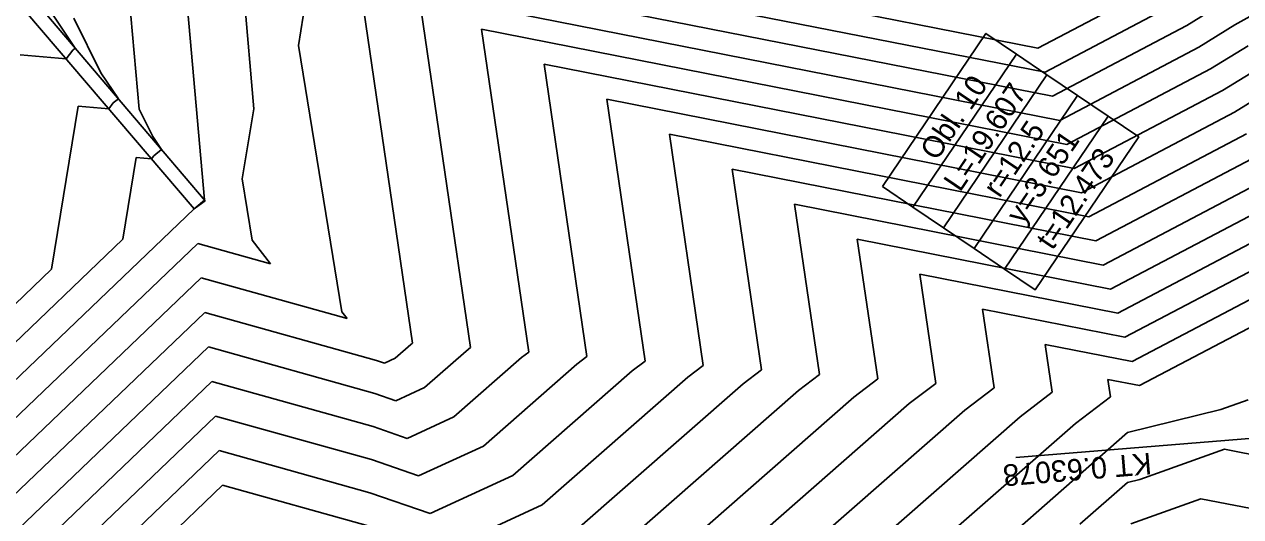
# Model space of a CAD drawing. Extents: x -549394 to -546608, y -1037055 to -1033629.
# Drawn here: x -547411.6 to -547213.9, y -1036111.6 to -1036031.6 of the extents above; entities that cross this region are included whole.
import ezdxf

# ---------------------------------------------------------------- set-up
doc = ezdxf.new("R2010")
doc.units = 0
for name, color, linetype in [('hlavni_vrst', 7, 'Continuous'), ('hrana_L', 7, 'Continuous'), ('norm_vrst', 7, 'Continuous'), ('x_popis_oblouky_C31', 7, 'Continuous')]:
    doc.layers.add(name, color=color, linetype=linetype)

msp = doc.modelspace()

# ---------------------------------------------------------------- linework, layer by layer
at = {"layer": 'hlavni_vrst'}
for p, q in [((-547385.56, -1036022.8), (-547382.3, -1036060.1)), ((-547337.27, -1036032.37), (-547329.59, -1036084.85)), ((-547242.13, -1036051.11), (-547337.27, -1036032.37)), ((-547212.7, -1036035.07), (-547218.78, -1036038.81)), ((-547218.78, -1036038.81), (-547242.13, -1036051.11)), ((-547209.1, -1036056.41), (-547236.25, -1036070.69)), ((-547382.26, -1036060.17), (-547383.95, -1036061.55)), ((-547382.3, -1036060.1), (-547382.27, -1036060.15)), ((-547382.27, -1036060.15), (-547382.26, -1036060.17)), ((-547286.38, -1036060.82), (-547282.33, -1036088.47)), ((-547236.25, -1036070.69), (-547286.38, -1036060.82)), ((-547383.95, -1036061.55), (-547529.34, -1036200.56)), ((-547383.95, -1036061.55), (-547383.95, -1036061.55)), ((-547383.95, -1036061.55), (-547383.95, -1036061.55)), ((-547383.95, -1036061.55), (-547383.95, -1036061.55)), ((-547383.95, -1036061.55), (-547383.95, -1036061.55)), ((-547383.95, -1036061.55), (-547383.95, -1036061.55)), ((-547383.95, -1036061.55), (-547383.95, -1036061.55)), ((-547383.95, -1036061.55), (-547383.95, -1036061.55)), ((-547206.64, -1036077.79), (-547230.36, -1036090.28)), ((-547330.76, -1036085.74), (-547341.74, -1036095.35)), ((-547329.59, -1036084.85), (-547330.76, -1036085.74)), ((-547282.33, -1036088.47), (-547285.75, -1036091.08)), ((-547381.07, -1036089.63), (-547506.12, -1036209.19)), ((-547354.88, -1036096.94), (-547381.07, -1036089.63)), ((-547235.49, -1036089.27), (-547235.08, -1036092.1)), ((-547230.36, -1036090.28), (-547235.49, -1036089.27)), ((-547285.75, -1036091.08), (-547317.86, -1036119.19)), ((-547235.08, -1036092.1), (-547240.75, -1036096.43)), ((-547341.74, -1036095.35), (-547349.34, -1036098.86)), ((-547240.75, -1036096.43), (-547293.98, -1036143.02)), ((-547349.34, -1036098.86), (-547354.88, -1036096.94))]:
    msp.add_line(p, q, dxfattribs=at)
at = {"layer": 'hrana_L'}
for p, q in [((-547382.19, -1036060.25), (-547409.46, -1036028.18)), ((-547411.32, -1036029.57), (-547383.95, -1036061.55)), ((-547383.95, -1036061.55), (-547382.19, -1036060.25))]:
    msp.add_line(p, q, dxfattribs=at)
at = {"layer": 'norm_vrst'}
for p, q in [((-547158.79, -1036000.4), (-547214.84, -1036031.67)), ((-547246.84, -1036035.44), (-547355.52, -1036014.04)), ((-547245.66, -1036039.35), (-547358.4, -1036017.15)), ((-547357.62, -1036020.99), (-547348.49, -1036083.4)), ((-547244.48, -1036043.27), (-547357.62, -1036020.99)), ((-547376.33, -1036021.55), (-547374.26, -1036045.33)), ((-547394.78, -1036024.05), (-547392.92, -1036045.34)), ((-547226.52, -1036024.74), (-547246.84, -1036035.44)), ((-547347.44, -1036026.68), (-547339.04, -1036084.12)), ((-547243.31, -1036047.19), (-547347.44, -1036026.68)), ((-547407.54, -1036029.1), (-547403.29, -1036035.43)), ((-547224.58, -1036028.26), (-547245.66, -1036039.35)), ((-547216.97, -1036028.27), (-547222.65, -1036031.78)), ((-547403.54, -1036030.58), (-547399.12, -1036039.45)), ((-547366.24, -1036030.25), (-547367.03, -1036035)), ((-547222.65, -1036031.78), (-547244.48, -1036043.27)), ((-547214.84, -1036031.67), (-547220.71, -1036035.3)), ((-547367.03, -1036035), (-547359.98, -1036078.3)), ((-547220.71, -1036035.3), (-547243.31, -1036047.19)), ((-547404.79, -1036037.2), (-547412.23, -1036036.52)), ((-547403.67, -1036035.75), (-547404.79, -1036037.2)), ((-547403.29, -1036035.43), (-547403.67, -1036035.75)), ((-547327.09, -1036038.06), (-547320.14, -1036085.57)), ((-547240.95, -1036055.02), (-547327.09, -1036038.06)), ((-547210.57, -1036038.46), (-547216.84, -1036042.33)), ((-547399.12, -1036039.45), (-547396.28, -1036043.68)), ((-547216.84, -1036042.33), (-547240.95, -1036055.02)), ((-547208.44, -1036041.86), (-547214.91, -1036045.85)), ((-547402.8, -1036044.86), (-547407.14, -1036071.39)), ((-547397.84, -1036045.32), (-547402.8, -1036044.86)), ((-547397.1, -1036044.35), (-547397.84, -1036045.32)), ((-547396.28, -1036043.68), (-547397.1, -1036044.35)), ((-547316.91, -1036043.75), (-547310.69, -1036086.3)), ((-547239.78, -1036058.94), (-547316.91, -1036043.75)), ((-547392.92, -1036045.34), (-547390.7, -1036049.8)), ((-547374.26, -1036045.33), (-547376.15, -1036056.66)), ((-547214.91, -1036045.85), (-547239.78, -1036058.94)), ((-547390.7, -1036049.8), (-547389.27, -1036051.92)), ((-547306.73, -1036049.44), (-547301.23, -1036087.02)), ((-547238.6, -1036062.86), (-547306.73, -1036049.44)), ((-547212.97, -1036049.37), (-547238.6, -1036062.86)), ((-547390.52, -1036052.95), (-547390.9, -1036053.43)), ((-547389.27, -1036051.92), (-547390.52, -1036052.95)), ((-547211.04, -1036052.89), (-547237.42, -1036066.77)), ((-547393.38, -1036053.21), (-547395.55, -1036066.47)), ((-547390.9, -1036053.43), (-547393.38, -1036053.21)), ((-547296.56, -1036055.13), (-547291.78, -1036087.75)), ((-547237.42, -1036066.77), (-547296.56, -1036055.13)), ((-547376.15, -1036056.66), (-547374.52, -1036066.65)), ((-547207.17, -1036059.92), (-547235.07, -1036074.61)), ((-547205.23, -1036063.44), (-547233.89, -1036078.53)), ((-547395.55, -1036066.47), (-547533.98, -1036198.84)), ((-547374.52, -1036066.65), (-547371.54, -1036070.47)), ((-547276.2, -1036066.51), (-547272.88, -1036089.2)), ((-547235.07, -1036074.61), (-547276.2, -1036066.51)), ((-547203.3, -1036066.96), (-547232.71, -1036082.44)), ((-547383.37, -1036067.17), (-547524.69, -1036202.29)), ((-547371.54, -1036070.47), (-547383.37, -1036067.17)), ((-547201.37, -1036070.48), (-547231.54, -1036086.36)), ((-547407.14, -1036071.39), (-547538.63, -1036197.11)), ((-547382.8, -1036072.78), (-547520.05, -1036204.01)), ((-547359.12, -1036079.39), (-547382.8, -1036072.78)), ((-547266.02, -1036072.2), (-547263.43, -1036089.92)), ((-547233.89, -1036078.53), (-547266.02, -1036072.2)), ((-547382.22, -1036078.4), (-547515.4, -1036205.74)), ((-547354.33, -1036086.19), (-547382.22, -1036078.4)), ((-547359.98, -1036078.3), (-547359.12, -1036079.39)), ((-547255.85, -1036077.89), (-547253.98, -1036090.65)), ((-547232.71, -1036082.44), (-547255.85, -1036077.89)), ((-547381.64, -1036084.01), (-547510.76, -1036207.47)), ((-547354.6, -1036091.56), (-547381.64, -1036084.01)), ((-547348.76, -1036083.6), (-547351.29, -1036085.82)), ((-547348.49, -1036083.4), (-547348.76, -1036083.6)), ((-547339.76, -1036084.67), (-547346.52, -1036090.59)), ((-547339.04, -1036084.12), (-547339.76, -1036084.67)), ((-547245.67, -1036083.58), (-547244.53, -1036091.37)), ((-547231.54, -1036086.36), (-547245.67, -1036083.58)), ((-547353.05, -1036086.63), (-547354.33, -1036086.19)), ((-547351.29, -1036085.82), (-547353.05, -1036086.63)), ((-547320.14, -1036085.57), (-547321.76, -1036086.81)), ((-547310.69, -1036086.3), (-547312.76, -1036087.88)), ((-547321.76, -1036086.81), (-547336.97, -1036100.12)), ((-547312.76, -1036087.88), (-547332.19, -1036104.89)), ((-547301.23, -1036087.02), (-547303.76, -1036088.94)), ((-547291.78, -1036087.75), (-547294.76, -1036090.01)), ((-547346.52, -1036090.59), (-547351.19, -1036092.74)), ((-547303.76, -1036088.94), (-547327.42, -1036109.66)), ((-547294.76, -1036090.01), (-547322.64, -1036114.42)), ((-547272.88, -1036089.2), (-547276.75, -1036092.15)), ((-547263.43, -1036089.92), (-547267.75, -1036093.22)), ((-547253.98, -1036090.65), (-547258.75, -1036094.29)), ((-547351.19, -1036092.74), (-547354.6, -1036091.56)), ((-547276.75, -1036092.15), (-547313.09, -1036123.96)), ((-547244.53, -1036091.37), (-547249.75, -1036095.36)), ((-547212.67, -1036092.59), (-547217.14, -1036094.19)), ((-547267.75, -1036093.22), (-547308.31, -1036128.72)), ((-547258.75, -1036094.29), (-547303.54, -1036133.49)), ((-547217.14, -1036094.19), (-547232.29, -1036097.92)), ((-547380.49, -1036095.24), (-547501.47, -1036210.92)), ((-547355.15, -1036102.32), (-547380.49, -1036095.24)), ((-547249.75, -1036095.36), (-547298.76, -1036138.26)), ((-547232.29, -1036097.92), (-547263.21, -1036125.03)), ((-547336.97, -1036100.12), (-547347.49, -1036104.97)), ((-547379.92, -1036100.86), (-547496.83, -1036212.64)), ((-547355.43, -1036107.7), (-547379.92, -1036100.86)), ((-547347.49, -1036104.97), (-547355.15, -1036102.32)), ((-547216.52, -1036100.64), (-547230.31, -1036105.55)), ((-547209.69, -1036101.97), (-547216.52, -1036100.64)), ((-547379.34, -1036106.47), (-547492.18, -1036214.37)), ((-547355.7, -1036113.07), (-547379.34, -1036106.47)), ((-547332.19, -1036104.89), (-547345.63, -1036111.08)), ((-547232.29, -1036106.04), (-547240.02, -1036112.82)), ((-547230.31, -1036105.55), (-547232.29, -1036106.04)), ((-547345.63, -1036111.08), (-547355.43, -1036107.7)), ((-547327.42, -1036109.66), (-547343.78, -1036117.2)), ((-547220.38, -1036108.68), (-547231.74, -1036112.73)), ((-547208.93, -1036110.91), (-547220.38, -1036108.68))]:
    msp.add_line(p, q, dxfattribs=at)
at = {"layer": 'x_popis_oblouky_C31'}
for points in [[(-547272.13, -1036057.91), (-547255.31, -1036033.06), (-547250.34, -1036036.43), (-547267.16, -1036061.27)], [(-547267.16, -1036061.27), (-547250.34, -1036036.43), (-547245.38, -1036039.79), (-547262.19, -1036064.63)], [(-547262.19, -1036064.63), (-547245.38, -1036039.79), (-547240.41, -1036043.15), (-547257.22, -1036068)], [(-547257.22, -1036068), (-547240.41, -1036043.15), (-547235.44, -1036046.52), (-547252.26, -1036071.36)], [(-547252.26, -1036071.36), (-547235.44, -1036046.52), (-547230.47, -1036049.88), (-547247.29, -1036074.72)]]:
    msp.add_lwpolyline(points, close=True, dxfattribs=at)
msp.add_lwpolyline([(-547209.19, -1036098.59), (-547250.42, -1036101.99)], dxfattribs=at)

# ---------------------------------------------------------------- texts
for s, rotation, p in [('Obl. 10', 55.9269, (-547263.32, -1036053.91)), ('L=19.607', 55.9269, (-547259.5, -1036058.97)), ('r=12.5', 55.9269, (-547253.1, -1036059.92)), ('y=3.651', 55.9269, (-547249.35, -1036064.29)), ('t=12.473', 55.9269, (-547244.48, -1036068.43)), ('KT 0.63078', 184.7093, (-547228.53, -1036101.19))]:
    msp.add_text(s, height=3.5, rotation=rotation, dxfattribs=at).set_placement(p)

doc.saveas('drawing.dxf')
